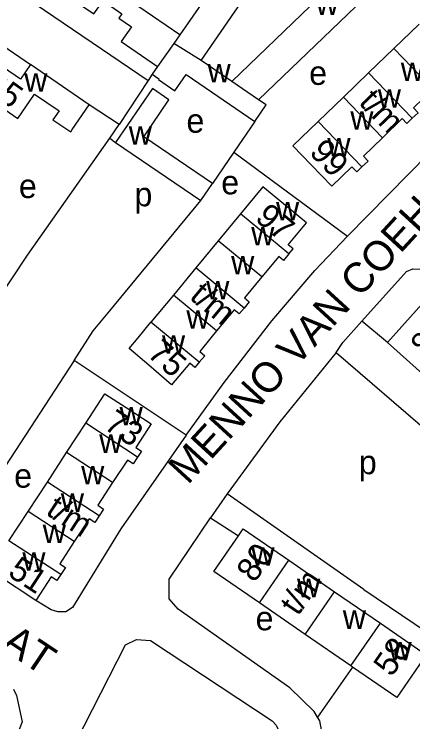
# Model space of a CAD drawing. Extents: x 159294 to 161936, y 384538 to 386517.
# Drawn here: x 160202.6 to 160269, y 385435.9 to 385554 of the extents above; entities that cross this region are included whole.
import ezdxf

# ---------------------------------------------------------------- set-up
doc = ezdxf.new("R2010")
doc.units = 0
for name, color, linetype in [('BLT_Basislijn', 7, 'Continuous'), ('BLT_Bebouwing', 7, 'Continuous'), ('BLT_Centroide', 7, 'Continuous'), ('BLT_Huisnummer', 7, 'Continuous'), ('BLT_Huisnummer_reeks', 7, 'Continuous'), ('BLT_Onderverdeling_panden', 7, 'Continuous'), ('BLT_Straatnaam', 7, 'Continuous')]:
    doc.layers.add(name, color=color, linetype=linetype)

msp = doc.modelspace()

# ---------------------------------------------------------------- linework, layer by layer
at = {"layer": 'BLT_Basislijn'}
for p, q in [((160198.17, 385561.15), (160224.94, 385542.97)), ((160193.16, 385554), (160205.3, 385545.6)), ((160225.61, 385544), (160224.94, 385542.97)), ((160224.94, 385542.97), (160220.09, 385535.58)), ((160220.09, 385535.58), (160215.09, 385538.91)), ((160218.51, 385533.32), (160220.09, 385535.58)), ((160242.68, 385536.13), (160239.2, 385531.01)), ((160204.83, 385513.8), (160218.51, 385533.32)), ((160218.51, 385533.32), (160219.48, 385532.6)), ((160239.2, 385531.01), (160235.62, 385525.75)), ((160239.2, 385531.01), (160258.12, 385516.97)), ((160218.51, 385504.49), (160233.69, 385522.91)), ((160183.74, 385482.26), (160204.83, 385513.8)), ((160264.79, 385499.25), (160260.53, 385502.78)), ((160256.26, 385497.54), (160277.26, 385479.41)), ((160231.26, 385483.77), (160212.59, 385496.2)), ((160238.11, 385473.96), (160235.33, 385469.95)), ((160260.89, 385458.02), (160238.11, 385473.96)), ((160235.33, 385469.95), (160239.95, 385466.99)), ((160259, 385445.07), (160253.14, 385436.72))]:
    msp.add_line(p, q, dxfattribs=at)
for points in [[(160285.87, 385544.31), (160275.15, 385534.25), (160258.12, 385516.97)], [(160231.26, 385483.77), (160237.59, 385492.58), (160245.51, 385502.86), (160252.67, 385511.27), (160258.12, 385516.97)], [(160260.53, 385502.78), (160267.96, 385511.09), (160269.01, 385511.52), (160271.92, 385511.4), (160301.72, 385484.87)], [(160212.59, 385496.2), (160215.73, 385501.15), (160218.51, 385504.49)], [(160256.26, 385497.54), (160257.36, 385499.23), (160260.53, 385502.78)], [(160256.26, 385497.54), (160246.84, 385486), (160238.11, 385473.96)], [(160212.59, 385496.2), (160194.65, 385468.77), (160192.38, 385464.92)], [(160231.26, 385483.77), (160220.36, 385468.11), (160212.33, 385455), (160211.22, 385454.27), (160209.87, 385454.27), (160208.77, 385454.61), (160206.2, 385456.2)], [(160253.14, 385436.72), (160252.56, 385437.64), (160248.52, 385441.6), (160229.93, 385454.72), (160228.43, 385456.47), (160228.43, 385459.75), (160235.33, 385469.95)], [(160260.89, 385458.02), (160273.52, 385449.42), (160274.17, 385449.4)], [(160229.49, 385405.57), (160225.41, 385400.07), (160222, 385399.59), (160204.56, 385402.68), (160203.51, 385403.47), (160202.65, 385404.68), (160202.97, 385408.18), (160203.67, 385410.35), (160210.13, 385427.22), (160221.17, 385448.8), (160222.96, 385449.64), (160225.33, 385449.52), (160245.56, 385436.12), (160246.27, 385435.37), (160247.21, 385433.33), (160246.89, 385430.78), (160229.49, 385405.57)], [(160202.46, 385441.36), (160203, 385440.33), (160203.93, 385435.95), (160195.7, 385414.98), (160189.15, 385395.09), (160188.4, 385393.51), (160185.94, 385391.47), (160181.74, 385391.95), (160180.93, 385392.51)], [(160224.65, 385393.03), (160228.18, 385393.81), (160229, 385394.25), (160231.88, 385397.05), (160249.85, 385423.12), (160252.6, 385427.1), (160253.9, 385429.73), (160254.1, 385433.11), (160253.53, 385436.12), (160253.14, 385436.72)]]:
    msp.add_lwpolyline(points, dxfattribs=at)
at = {"layer": 'BLT_Bebouwing'}
for p, q in [((160230.2, 385550.55), (160216.2, 385560.17)), ((160237.2, 385560.75), (160230.2, 385550.55)), ((160270.06, 385552.35), (160265.86, 385548.28)), ((160265.86, 385548.28), (160261.65, 385544.22)), ((160205.3, 385545.6), (160203.64, 385543.17)), ((160215.09, 385538.91), (160205.3, 385545.6)), ((160226.5, 385545.3), (160225.61, 385544)), ((160261.65, 385544.22), (160257.45, 385540.16)), ((160257.45, 385540.16), (160253.25, 385536.1)), ((160233.69, 385522.91), (160235.62, 385525.75)), ((160240.33, 385520.72), (160236.59, 385516.19)), ((160236.59, 385516.19), (160232.86, 385511.67)), ((160232.86, 385511.67), (160229.12, 385507.14)), ((160229.12, 385507.14), (160225.39, 385502.62)), ((160211.32, 385480.85), (160214.52, 385485.76)), ((160208.12, 385475.94), (160211.32, 385480.85)), ((160204.92, 385471.03), (160208.12, 385475.94)), ((160201.71, 385466.12), (160204.92, 385471.03)), ((160248.37, 385462.89), (160256, 385457.64)), ((160206.2, 385456.2), (160198.51, 385461.21)), ((160256, 385457.64), (160263.62, 385452.38)), ((160251.09, 385450.52), (160243.47, 385455.77)), ((160258.72, 385445.27), (160251.09, 385450.52)), ((160259, 385445.07), (160258.72, 385445.27))]:
    msp.add_line(p, q, dxfattribs=at)
for points in [[(160233.76, 385546.29), (160247.09, 385565.7), (160248.99, 385564.4), (160253.35, 385570.76), (160247.94, 385574.47)], [(160264.99, 385567.99), (160238.87, 385542.78)], [(160208.86, 385565.24), (160208.2, 385564.27), (160207.57, 385564.7), (160205.89, 385562.24), (160206.51, 385561.81), (160205.89, 385560.91), (160215.89, 385554.05), (160217.41, 385556.26), (160220.56, 385554.1), (160220.05, 385553.36), (160222.14, 385551.92), (160220.44, 385549.46), (160226.5, 385545.3)], [(160243.32, 385539.73), (160267.67, 385563.22)], [(160203.64, 385543.17), (160196.89, 385547.78), (160196.52, 385547.24), (160195.87, 385547.29), (160194.84, 385545.79), (160195.14, 385545.17), (160193.72, 385543.09)], [(160238.87, 385542.78), (160233.76, 385546.29)], [(160225.61, 385544), (160226.72, 385543.21), (160226.62, 385543.11), (160229.39, 385541.23), (160231.27, 385543.96), (160242.68, 385536.13)], [(160235.62, 385525.75), (160224.18, 385533.55), (160228.39, 385539.73), (160225.62, 385541.62), (160219.48, 385532.6)], [(160272.38, 385541.51), (160269.12, 385538.37), (160269.89, 385537.58), (160268.94, 385536.66)], [(160201.01, 385538.11), (160203.21, 385536.61), (160205.99, 385540.67), (160210.07, 385537.89), (160209.06, 385536.41), (160212.01, 385534.39), (160212.27, 385534.78), (160215.09, 385538.91)], [(160242.68, 385536.13), (160244.56, 385538.88), (160243.32, 385539.73)], [(160268.94, 385536.66), (160268.04, 385535.79), (160267.27, 385536.59), (160263.96, 385533.4)], [(160253.25, 385536.1), (160249.03, 385532.02), (160252.06, 385528.89), (160255.53, 385525.3), (160258.88, 385528.53), (160259.69, 385527.69), (160260.54, 385528.52)], [(160263.96, 385533.4), (160260.78, 385530.32), (160261.57, 385529.51), (160260.54, 385528.52)], [(160219.48, 385532.6), (160233.69, 385522.91)], [(160248.38, 385514.02), (160249.09, 385514.88), (160248.28, 385515.55), (160251.31, 385519.21), (160247.45, 385522.39), (160244.04, 385525.21), (160240.33, 385520.72)], [(160248.38, 385514.02), (160247.48, 385512.93), (160246.67, 385513.6), (160243.84, 385510.17)], [(160243.84, 385510.17), (160240.95, 385506.66), (160241.75, 385506), (160240.91, 385504.97)], [(160277.96, 385500.05), (160271.05, 385506.17), (160264.79, 385499.25)], [(160240.91, 385504.97), (160240.1, 385503.99), (160239.24, 385504.7), (160236.33, 385501.15)], [(160233.44, 385495.92), (160232.71, 385495.06), (160231.87, 385495.78), (160228.8, 385492.15), (160225.02, 385495.43), (160221.78, 385498.24), (160223.23, 385500), (160225.39, 385502.62)], [(160236.33, 385501.15), (160235.39, 385500), (160233.52, 385497.73), (160234.36, 385497.01), (160233.44, 385495.92)], [(160264.79, 385499.25), (160271.67, 385493.06)], [(160214.52, 385485.76), (160217.72, 385490.66), (160221.23, 385488.37), (160225.42, 385485.64), (160222.86, 385481.72), (160223.8, 385481.11), (160223.16, 385480.12)], [(160223.16, 385480.12), (160222.42, 385478.99), (160221.46, 385479.62), (160219, 385475.84)], [(160219, 385475.84), (160216.53, 385472.06), (160217.49, 385471.43), (160216.75, 385470.3)], [(160216.75, 385470.3), (160216.04, 385469.21), (160215.09, 385469.83), (160212.6, 385466.02)], [(160239.95, 385466.99), (160240.75, 385468.14), (160248.37, 385462.89)], [(160243.47, 385455.77), (160235.84, 385461.02), (160239.95, 385466.99)], [(160212.6, 385466.02), (160210.18, 385462.32), (160211.13, 385461.7), (160210.34, 385460.49)], [(160210.34, 385460.49), (160209.71, 385459.52), (160208.77, 385460.13), (160206.2, 385456.2)], [(160263.62, 385452.38), (160271.25, 385447.13), (160266.34, 385440.01), (160259, 385445.07)]]:
    msp.add_lwpolyline(points, dxfattribs=at)
at = {"layer": 'BLT_Onderverdeling_panden'}
for p, q in [((160230.2, 385550.55), (160229.2, 385549.13)), ((160229.2, 385549.13), (160226.5, 385545.3)), ((160233.76, 385546.29), (160229.2, 385549.13)), ((160272.38, 385541.51), (160265.86, 385548.28)), ((160268.94, 385536.66), (160261.65, 385544.22)), ((160243.32, 385539.73), (160238.87, 385542.78)), ((160263.96, 385533.4), (160257.45, 385540.16)), ((160260.54, 385528.52), (160253.25, 385536.1)), ((160248.38, 385514.02), (160240.33, 385520.72)), ((160243.84, 385510.17), (160236.59, 385516.19)), ((160240.91, 385504.97), (160232.86, 385511.67)), ((160236.33, 385501.15), (160229.12, 385507.14)), ((160233.44, 385495.92), (160225.39, 385502.62)), ((160223.16, 385480.12), (160214.52, 385485.76)), ((160219, 385475.84), (160211.32, 385480.85)), ((160216.75, 385470.3), (160208.12, 385475.94)), ((160212.6, 385466.02), (160204.92, 385471.03)), ((160210.34, 385460.49), (160201.71, 385466.12)), ((160243.47, 385455.77), (160248.37, 385462.89)), ((160251.09, 385450.52), (160256, 385457.64)), ((160258.72, 385445.27), (160263.62, 385452.38))]:
    msp.add_line(p, q, dxfattribs=at)

# ---------------------------------------------------------------- texts
at = {"layer": 'BLT_Centroide'}
for s, p in [('w', (160252.83, 385553.88)), ('w', (160267.02, 385542.88)), ('w', (160234.81, 385542.62)), ('e', (160251.75, 385542.22)), ('w', (160204.27, 385541.09)), ('w', (160263.19, 385538.41)), ('w', (160258.61, 385534.75)), ('e', (160231.3, 385534.23)), ('w', (160221.68, 385532.25)), ('w', (160254.78, 385530.28)), ('e', (160237.1, 385523.95)), ('e', (160203.38, 385523.33)), ('p', (160222.64, 385521.96)), ('w', (160246.23, 385519.62)), ('w', (160242.09, 385515.44)), ('w', (160238.75, 385510.59)), ('w', (160234.59, 385506.41)), ('w', (160231.28, 385501.53)), ('w', (160227.22, 385497.38)), ('w', (160220.16, 385485.38)), ('w', (160216.76, 385480.81)), ('p', (160260.03, 385477.25)), ('w', (160213.75, 385475.56)), ('e', (160202.59, 385475)), ('w', (160210.36, 385470.97)), ('w', (160207.35, 385465.75)), ('w', (160242.11, 385461.97)), ('w', (160203.95, 385461.16)), ('w', (160249.73, 385456.72)), ('e', (160242.83, 385451.2)), ('w', (160257.36, 385451.44)), ('w', (160264.98, 385446.19))]:
    msp.add_text(s, height=4, dxfattribs=at).set_placement(p)
at = {"layer": 'BLT_Huisnummer'}
msp.add_text('165', height=4, rotation=324.2812, dxfattribs=at).set_placement((160194.9, 385543.3))
at = {"layer": 'BLT_Huisnummer_reeks'}
for s, rotation, p in [('t/m', 314.0114, (160259.87, 385539.16)), ('99', 314.0114, (160251.62, 385530.83)), ('97', 320.2463, (160242.56, 385519.7)), ('t/m', 320.2453, (160231.64, 385506.62)), ('82', 48.0294, (160271.25, 385496.57)), ('75', 319.0469, (160224.58, 385497.09)), ('73', 326.8716, (160217.34, 385484.94)), ('t/m', 326.8711, (160207.67, 385470.66)), ('80', 55.444, (160242.65, 385459)), ('51', 326.8846, (160201.35, 385460.4)), ('t/m', 55.4403, (160249.88, 385453.46)), ('58', 55.4403, (160265.49, 385443.27))]:
    msp.add_text(s, height=4, rotation=rotation, dxfattribs=at).set_placement(p)
at = {"layer": 'BLT_Straatnaam'}
for s, rotation, p in [('MENNO VAN COEHOORNLAAN', 47.457, (160231.53, 385475.36)), ('VENNECOOLSTRAAT', 326.3091, (160150.39, 385481.47))]:
    msp.add_text(s, height=5, rotation=rotation, dxfattribs=at).set_placement(p)

doc.saveas('drawing.dxf')
